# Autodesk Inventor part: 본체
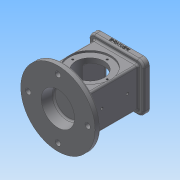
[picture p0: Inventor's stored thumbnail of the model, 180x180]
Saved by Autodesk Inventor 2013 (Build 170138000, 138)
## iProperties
Created: 2018-10
Part Number: 본체
Material: 일반
Document SubType Name: Modeling
Designer: Administrator
Density: 1 g/cm^3
Author: Administrator
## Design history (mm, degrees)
sketch "스케치1"
  geometry: L1 (-37, 33)-(37, 33); L2 (37, 33)-(37, -33); L3 (37, -33)-(-37, -33); L4 (-37, -33)-(-37, 33); L5 (-37, 33)-(37, -33); L6 (37, 33)-(-37, -33); 1 further point
  constraints: 12 end point, 2 midpoint, 2 parallel, 1 horizontal, 1 perpendicular
  dimensions: "d0" = 74 distance of L2.end L3.end; "d1" = 66 distance of L1.end L2.end
extrude "돌출1" new body sketch "스케치1" stored distance "d2" = 108; taper "d3" = 0 deg
sketch "스케치2"
  geometry: L1 (37, 33)-(-37, 33) reference; L2 (-37, 33)-(-37, -33) reference; L3 (-37, -33)-(37, -33) reference; L4 (37, -33)-(37, 33) reference; C1 r 62.5 at (0, 0); 1 further point
  constraints: 1 centre point, 1 coincident
  dimensions: "d4" = 125 diameter of C1
extrude "돌출2" join sketch "스케치2" distance "d5" = 10; taper "d6" = 0 deg
sketch "스케치3"
  geometry: L1 (37, -33)-(37, 33) reference; L2 (37, 33)-(-37, 33) reference; L3 (-37, 33)-(-37, -33) reference; L4 (-37, -33)-(37, -33) reference; L5 (-46, -41)-(46, -41); L6 (46, -41)-(46, 41); L7 (46, 41)-(-46, 41); L8 (-46, 41)-(-46, -41); L9 (-46, -41)-(46, 41); L10 (46, -41)-(-46, 41); A1 r 10 centre (27, -23) between (27, -33) and (37, -23) reference; A2 r 10 centre (27, 23) between (37, 23) and (27, 33) reference; A3 r 10 centre (-27, 23) between (-27, 33) and (-37, 23) reference; A4 r 10 centre (-27, -23) between (-37, -23) and (-27, -33) reference; 1 further point
  constraints: 12 end point, 2 midpoint, 2 parallel, 1 horizontal, 1 perpendicular
  dimensions: "d8" = 92 distance of L7.end L6.end; "d9" = 82 distance of L6.end L5.end
extrude "돌출3" join sketch "스케치3" distance "d10" = 10; taper "d11" = 0 deg
fillet "모깎기2" dims "d12" = 10
fillet "모깎기3" dims "d13" = 3
fillet "모깎기4" dims "d14" = 3
sketch "스케치4"
  geometry: A1 r 10 centre (-36, 31) between (-36, 41) and (-46, 31) reference; 2 further points
  constraints: 1 coincident
hole "구멍1" sketch "스케치4" at (-36, 31) diameter "d15" = 3.242; stored, may be unused: countersink angle "d19" = 90 deg, drill point angle "d21" = 118 deg; dims "d16" = 4, "d17" = 4, "d18" = 2, "d20" = 6
sketch "스케치6"
  geometry: L1 (96.5, -13)-(-28.5, -13) reference; C1 r 35 at (34, 41); 1 further point
  constraints: 1 centre point, 1 coincident
  dimensions: "d24" = 70 diameter of C1; "d25" = 54 distance from line of L1 C1.centre
extrude "돌출4" cut sketch "스케치6" distance "d26" = 3; taper "d27" = 0 deg
sketch "스케치7"
  geometry: C1 r 35 at (0, 0) reference; 1 further point
  constraints: 1 vertical alignment
  dimensions: "d28" = 29 distance of C1.centre point (0, 29)
hole "구멍2" sketch "스케치7" at (0, 29) diameter "d29" = 3.242; stored, may be unused: countersink angle "d33" = 90 deg, drill point angle "d35" = 118 deg; dims "d30" = 4, "d31" = 4, "d32" = 2, "d34" = 6
fillet "모깎기5" dims "d39" = 3
sketch "스케치8"
  geometry: C1 r 59.5 at (0, 0) reference; 1 further point
  constraints: 1 vertical alignment
  dimensions: "d40" = 50 distance of C1.centre point (0, 50)
hole "구멍3" sketch "스케치8" at (0, 50) diameter "d41" = 9; stored, may be unused: countersink angle "d45" = 90 deg, drill point angle "d47" = 118 deg; dims "d42" = 4, "d43" = 4, "d44" = 2, "d46" = 6
sketch "스케치9"
  geometry: C1 r 62.5 at (0, 0) reference; C2 r 28 at (0, 0)
  constraints: 1 centre point, 1 coincident
  dimensions: "d51" = 56 diameter of C2
extrude "돌출5" cut sketch "스케치9" distance "d52" = 18; taper "d53" = -10 deg
fillet "모깎기6" dims "d54" = 3
sketch "스케치11"
  geometry: L1 (26, -26)-(-26, -26); L2 (-26, -26)-(-26, 26); L3 (-26, 26)-(26, 26); L4 (26, 26)-(26, -26); L5 (26, -26)-(-26, 26); L6 (-26, -26)-(26, 26); 1 further point
  constraints: 12 end point, 2 midpoint, 2 parallel, 1 horizontal, 1 perpendicular
  dimensions: "d58" = 52 distance of L2.end L3.end; "d59" = 52 distance of L1.end L2.end
extrude "돌출7" cut sketch "스케치11" distance "d60" = 8; taper "d61" = 0 deg
sketch "스케치12"
  geometry: L1 (-22, -22)-(22, -22); L2 (22, -22)-(22, 22); L3 (22, 22)-(-22, 22); L4 (-22, 22)-(-22, -22); L5 (-22, -22)-(22, 22); L6 (22, -22)-(-22, 22); 1 further point
  constraints: 12 end point, 2 midpoint, 2 parallel, 1 horizontal, 1 perpendicular
  dimensions: "d62" = 44 distance of L3.end L2.end; "d63" = 44 distance of L2.end L1.end
extrude "돌출8" cut sketch "스케치12" distance "d64" = 74; taper "d65" = 0 deg
fillet "모깎기7" dims "d66" = 3
fillet "모깎기8" dims "d67" = 3
chamfer "모따기1" distance "d68" = 1; stored, may be unused: second distance "d69" = 2, angle "d70" = 45 deg
sketch "스케치13"
  geometry: C1 r 35 at (0, 0) reference; C2 r 24 at (0, 0)
  constraints: 1 centre point, 1 coincident
  dimensions: "d71" = 48 diameter of C2
extrude "돌출9" cut sketch "스케치13" stored distance "d72" = 74; taper "d73" = 0 deg
sketch "스케치14"
  geometry: L1 (32.5, -13)-(-92.5, -13) reference; 3 further points
  constraints: 1 midpoint, 1 vertical alignment
  dimensions: "d74" = 37 distance from line of L1 point (-30, 24)
hole "구멍4" sketch "스케치14" at (-30, 24) diameter "d75" = 4.134; stored, may be unused: countersink angle "d79" = 90 deg, drill point angle "d81" = 0 deg; dims "d76" = 4, "d77" = 4, "d78" = 2, "d80" = 6
fillet "모깎기9" dims "d85" = 3
sketch "스케치15"
  geometry: L1 (0, 0)-(72, 0) reference; L2 (-10, 0)-(-10, -7) reference; 2 further points
  constraints: 1 other
  dimensions: "d86" = 46 distance from line of point (36, -4) L2; "d87" = 4 distance from line of L1 point (36, -4)
feature "엠보싱1" sketch "스케치15" dims "d0" = 74, "d1" = 66, "d88" = 0.5, "d89" = 0
node "솔리드1"
mirror "대칭1"
mirror "대칭2"
mirror "대칭3"
pattern_circular "원형 패턴1" dims angle "d37" = 360 deg
mirror "대칭4"
pattern_circular "원형 패턴2" dims angle "d49" = 360 deg
pattern_linear "직사각형 패턴1" dims "d84" = 43
